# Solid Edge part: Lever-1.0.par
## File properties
Author: wojci
Template: ISO Metric Part.par
Last saved by: Wojciech Szerszeń
Revision: 23
Application: Solid Edge
Username: wojci
Accuracy: 0.99000000000
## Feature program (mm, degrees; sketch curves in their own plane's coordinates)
sketch for "unnamed Protrusion 1" plane through (0, 0, 0) normal (0, -1, 0) x-axis (1, 0, 0)
  line (11.399, 3.7502) -> (33.5325, -1.1488)
  arc centre (32.2359, -7.0068) radius 5.9998 from (31.1064, -12.8993) to (33.5325, -1.1488) ccw
  line (-1.2787, -6.8822) -> (31.1064, -12.8993)
  line (-26.5, 8.4938) -> (-6.0467, 3.5266)
  arc centre (-29.1774, 6.9779) radius 12.105 from (-26.3206, 18.741) to (-40.0548, 1.6663) ccw
  line (-26.3206, 18.741) -> (2.832, 11.661)
extrude "unnamed Protrusion 1" add finite 27.5 along -normal
sketch for "ExtrudedCutout_1" plane through (-2.2401, 27.5, 3.5583) normal (0, 1, 0) x-axis (-0.983174, 0, 0.182671)
extrude "ExtrudedCutout_1" cut finite 8 along -normal
sketch for "unnamed Cutout 1" plane through (32.0198, 0, -7.9834) normal (-0.241922, 0, -0.970296) x-axis (-0.970296, 0, 0.241922)
  line (-7.5, 12.7) -> (-7.5, 5.4)
  line (7.5, 5.4) -> (-7.5, 5.4)
  line (7.5, 5.4) -> (7.5, 12.7)
  line (7.5, 12.7) -> (-7.5, 12.7)
extrude "unnamed Cutout 1" cut through along +normal
sketch for "ExtrudedProtrusion_3" plane through (-2.2401, 0, 3.5583) normal (0, -1, 0) x-axis (0.983174, 0, -0.182671)
  circle centre (2.8524, -3.0892) radius 12
extrude "ExtrudedProtrusion_3" add finite 12.5 along -normal
sketch for "ExtrudedCutout_4" plane through (-2.2401, 0, 3.5583) normal (0, -1, 0) x-axis (0.983174, 0, -0.182671)
  line (-24.7533, 0.4209) -> (-8.8531, -0.4471)
  bspline degree 3 poles (-8.8531, -0.4471) (-6.4526, 5.2837) (-3.2132, 8.4029) (0.9029, 9.0725) knots 0 1 multiplicities 4 4
  line (-26.4186, 10.7607) -> (0.9029, 9.0725)
  arc centre (-27.1688, -1.3804) radius 12.1642 from (-26.4186, 10.7607) to (-36.8328, -8.7678) ccw
extrude "ExtrudedCutout_4" cut finite 12.5 along -normal
sketch for "ExtrudedCutout_5" plane through (12.5099, 0, -0.3117) normal (0, -1, 0) x-axis (0.983174, 0, -0.182671)
  line (-1.2571, 3.7709) -> (-2.0002, -8.9787)
extrude "ExtrudedCutout_5" cut finite 2.5 along -normal
sketch for "ExtrudedCutout_6" plane through (-14.7469, 27.5, 5.718) normal (0, 1, 0) x-axis (-0.971754, 0, 0.235997)
  line (-8.9716, -0.0762) -> (-14.2058, -1.6368)
  line (-15.688, -3.6142) -> (-16.0614, -9.0658)
extrude "ExtrudedCutout_6" cut finite 15 along -normal
fillet "Round_1" radius 1
fillet "Round_2" radius 2
chamfer "Chamfer_3" setback 3.5
sketch for "ExtrudedProtrusion_4" plane through (-14.75, 27.5, 5.7186) normal (0, 1, 0) x-axis (-0.971754, 0, 0.235997)
  arc centre (-15.683, -2.0781) radius 12.0019 from (-15.683, 9.9238) to (-25.8005, -8.5342) ccw
  arc centre (-15.6837, -2.0785) radius 12.0011 from (-25.8005, -8.5342) to (-3.8508, -0.0762) ccw
  arc centre (-15.6852, -2.0788) radius 12.0027 from (-3.8508, -0.0762) to (-15.683, 9.9238) ccw
extrude "ExtrudedProtrusion_4" add finite 25 along +normal
sketch for "ExtrudedCutout_7" plane through (-1.8397, 27.5, -3.5559) normal (0, -1, 0) x-axis (0.983174, 0, -0.182671)
  line (-1.0366, 4.6195) -> (-5.43, 6.1949)
  arc centre (-0.6991, 5.5609) radius 1 from (-1.0366, 4.6195) to (0.0331, 4.8798) ccw
  arc centre (1.1592, 3.8322) radius 1.5381 from (0.0331, 4.8798) to (1.7263, 2.4025) cw
  arc centre (2.095, 1.4729) radius 1 from (1.0951, 1.4591) to (1.7263, 2.4025) cw
  line (1.1319, -1.1955) -> (1.0951, 1.4591)
  arc centre (3.1317, -1.1678) radius 2 from (1.1319, -1.1955) to (3.1317, -3.1678) ccw
  line (10.9097, -3.1678) -> (3.1317, -3.1678)
  arc centre (1.1598, 3.8297) radius 12.0011 from (-10.5463, 6.4742) to (10.9097, -3.1678) ccw
  line (-5.43, 6.1949) -> (-10.5463, 6.4742)
extrude "ExtrudedCutout_7" cut finite 1 along -normal  FiniteDepth2 = 17 mm
sketch for "Hole_3" plane through (0, 52.5, 0) normal (0, 1, 0) x-axis (-1, 0, 0)
  hole centre (0, 0) bore radius 1.7
hole "Hole_3" diameter 3.4 through
chamfer "Chamfer_4" setback 3
fillet "Round_4" radius 15
chamfer "Chamfer_6" setback 1.5
chamfer "Chamfer_7" setback 2
sketch for "Hole_4" plane through (24.6721, 0, -5.1821) normal (0, -1, 0) x-axis (0.983174, 0, -0.182671)
  hole centre (7.7357, -1.412) bore radius 1.2295
hole "Hole_4" nominal diameter 3 through  ThreadDepth = 2 mm
fillet "Round_5" radius 25
chamfer "Chamfer_8" setback 2.4
chamfer "Chamfer_9" setback 3
fillet "Round_6" radius 5.5
fillet "Round_7" radius 4
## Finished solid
Body 1: solid body, 55 faces, 143 edges, 86 vertices.
  Faces by surface: cylinder 21, plane 20, cone 11, spline 2, swept 1
  Edges by curve: line 67, circle 52, intersection 13, curve on surface 10, ellipse 1
Bounding box of the edges (mm; curved faces can reach further): 79.518 x 52.500 x 32.090, from (-41.2824, 0, -13.0066) to (38.2357, 52.5, 19.0829).
Cylindrical faces by radius (mm): R1 x2, R1.2295 x3, R1.7 x1, R2 x1, R4 x1, R5.5 x1, R5.9998 x2, R8.5 x1, R12 x2, R12.0011 x1, R12.0019 x1, R12.0027 x1, R12.003 x1, R12.105 x1, R15 x1, R25 x1
Conical faces (half-angle, radius in mm at the cone's reference point): 45 deg R10.0011 x1, 45 deg R10.0019 x1, 45 deg R10.0027 x1, 45 deg R12 x3, 45 deg R12.0011 x2, 45 deg R12.0027 x1, 45 deg R15.003 x1, 45 deg R17 x1
Planar faces by outward normal: +y 6, -y 5, oblique 9
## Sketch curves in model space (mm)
line (32.0198, 0, -7.9834) -> (32.0198, 19.5, -7.9834)
line (24.7425, 12.7, -6.169) -> (39.297, 12.7, -9.7978)
line (39.297, 12.7, -9.7978) -> (39.297, 5.4, -9.7978)
line (24.7425, 5.4, -6.169) -> (39.297, 5.4, -9.7978)
line (24.7425, 5.4, -6.169) -> (24.7425, 12.7, -6.169)
line (0, 0, 0) -> (-35, 0, 8.5)
line (0, 0, 0) -> (32.0198, 0, -7.9834)
line (0, 0, 0) -> (-35, 0, 0)
circle centre (32.0198, 0, -7.9834) radius 7
arc centre (32.2359, 0, -7.0068) radius 5.9998 from (31.1064, 0, -12.8993) through (38.1738, 0, -7.8663) to (33.5325, 0, -1.1488)
line (11.399, 0, 3.7502) -> (33.5325, 0, -1.1488)
arc centre (0, 0, 0) radius 12 from (2.832, 0, 11.661) through (8.141, 0, 8.8162) to (11.399, 0, 3.7502)
line (-26.3206, 0, 18.741) -> (2.832, 0, 11.661)
arc centre (-29.1774, 0, 6.9779) radius 12.105 from (-26.3206, 0, 18.741) through (-38.6097, 0, 14.5649) to (-40.0548, 0, 1.6663)
arc centre (-35, 0, 8.5) radius 8.5 from (-26.5, 0, 8.4938) through (-31.4043, 0, 0.798) to (-40.0548, 0, 1.6663)
line (-26.5, 0, 8.4938) -> (-6.0467, 0, 3.5266)
arc centre (0, 0, 0) radius 7 from (-1.2787, 0, -6.8822) through (-6.3641, 0, -2.9152) to (-6.0467, 0, 3.5266)
line (-1.2787, 0, -6.8822) -> (31.1064, 0, -12.8993)
circle centre (32.0198, 0, -7.9834) radius 5
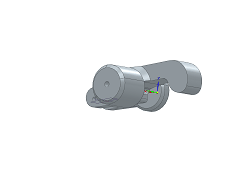
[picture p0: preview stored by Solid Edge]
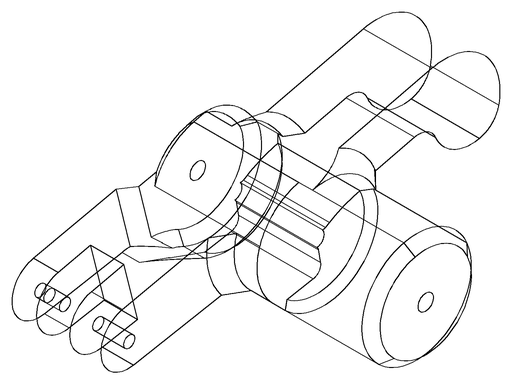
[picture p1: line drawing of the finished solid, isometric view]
